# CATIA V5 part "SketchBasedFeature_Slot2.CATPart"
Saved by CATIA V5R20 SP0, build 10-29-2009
Part number: Part1
Bounding box of the stored display mesh (mm): x -1.957 to 282, y -12.257 to 12.257, z -12.257 to 13.91
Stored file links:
  G:\카티아자료\수업자료\툴바예제\2 PartDesign\upload2\SketchBasedFeature_Slot.CATPart
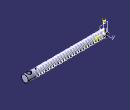
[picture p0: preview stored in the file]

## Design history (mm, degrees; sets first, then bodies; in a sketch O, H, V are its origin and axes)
AxisSystem1: origin (0, 0, 0), X (1, 0, 0), Y (0, 1, 0), Z (0, 0, 1)
Body1 (main body)
  Sketch1 on YZ plane of AxisSystem1, origin (0, 0, 0), H (0, 1, 0), V (0, 0, 1)
    circle A1 centre (0, 0) radius 12.257
  Pad1: profile Sketch1, direction (1, 0, 0), length 282
  Sketch2 on XY plane of AxisSystem1, origin (0, 0, 0), H (1, 0, 0), V (0, 1, 0)
    circle A1 centre (268.0259, 0) radius 7.0672
    point P1 (268.0259, 0)
    coincidence: P1 H
  Pocket1: profile Sketch2, direction (0, 0, -1), length 282, mirrored extent
  Sketch3 on ZX plane of AxisSystem1, origin (0, 0, 0), H (0, 0, 1), V (1, 0, 0)
    line L1 (12.257, 0) -> (12.257, 260.9588)
    point P1 (12.257, 0)
  Helix1: Direction edge [XY plane of AxisSystem1 | ZX plane of AxisSystem1], RefPoint Sketch3.P1, Pitch 9, Height 243, TaperAngle 0, RadiusLaw Sketch3
  Plane1: type Normal, Curve Helix1, RefPoint Sketch3.P1
  Sketch4 on Plane1, origin (0, 0, 0), H (0.9932, 0.1161, 0), V (0, 0, 1)
    line L1 (-1.9706, 13.9098) -> (1.5511, 13.9098)
    line L2 (1.5511, 13.9098) -> (1.5511, 10.4438)
    line L3 (1.5511, 10.4438) -> (-1.9706, 10.4438)
    line L4 (-1.9706, 10.4438) -> (-1.9706, 13.9098)
    horizontal: L1 H, L3 H
    vertical: L2 V, L4 V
